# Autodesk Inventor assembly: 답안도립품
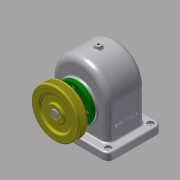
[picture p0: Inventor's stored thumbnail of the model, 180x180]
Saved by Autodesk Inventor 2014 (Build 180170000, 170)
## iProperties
Created: 2016-10
Part Number: 답안도립품
Document SubType Name: Assembly
Designer: SCD-A13
Author: SCD-A13
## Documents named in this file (15)
- C:\Users\SCD-A13\Desktop\461007V1010\답안도립품.iam
- C:\Users\SCD-A13\Desktop\461007V1010\본체.ipt
- C:\Users\SCD-A13\Desktop\461007V1010\축.ipt
- C:\Users\SCD-A13\Desktop\461007V1010\키 - 5 x 5 x 18.ipt
- C:\Users\SCD-A13\Desktop\461007V1010\키 - 6 x 6 x 22.ipt
- C:\Users\SCD-A13\Desktop\461007V1010\베어링 6203.ipt
- C:\Users\SCD-A13\Desktop\461007V1010\스퍼기어.ipt
- C:\Users\SCD-A13\Desktop\461007V1010\뒤커버.ipt
- C:\Users\SCD-A13\Desktop\461007V1010\앞커버.ipt
- C:\Users\SCD-A13\Desktop\461007V1010\볼트 M3 x 10.ipt
- C:\Users\SCD-A13\Desktop\461007V1010\볼트 M3 x 8.ipt
- C:\Users\SCD-A13\Desktop\461007V1010\부시.ipt
- C:\Users\SCD-A13\Desktop\461007V1010\오일씰 28 40 8.ipt
- C:\Users\SCD-A13\Desktop\461007V1010\V-벨트풀리.ipt
- C:\Users\SCD-A13\Desktop\461007V1010\멈춤나사 - M4x10.ipt
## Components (9 placed, 3 different names)
1. V-벨트풀리:1
2. ISO 4762 M3 x 8:1
3. ISO 4762 M3 x 8:2
4. ISO 4762 M3 x 8:3
5. ISO 4762 M3 x 8:4
6. ISO 4762 M3 x 10:1
7. ISO 4762 M3 x 10:2
8. ISO 4762 M3 x 10:3
9. ISO 4762 M3 x 10:4
